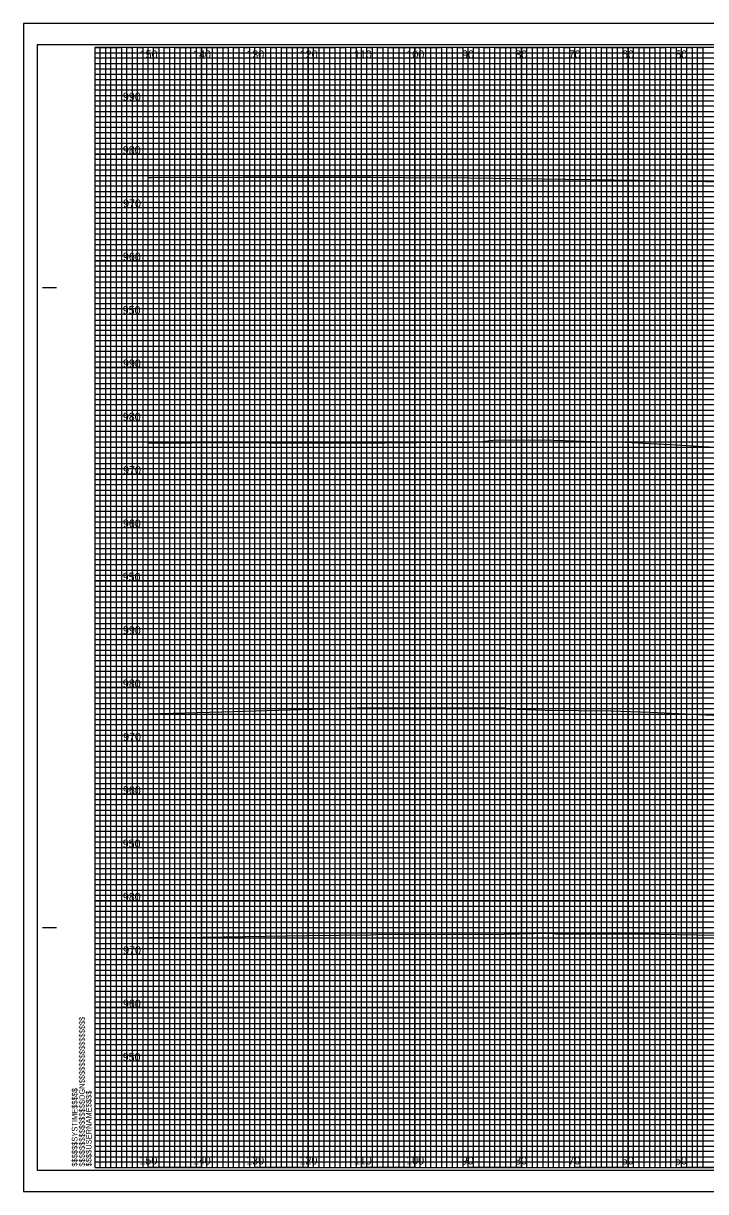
# Model space of a CAD drawing. Extents: x -13 to 760, y -5 to 1491.
# Drawn here: x 423.3 to 551.2, y -4.5 to 214.5 of the extents above; entities that cross this region are included whole.
import ezdxf

# ---------------------------------------------------------------- set-up
doc = ezdxf.new("R2010")
doc.units = 0
for name, color, linetype in [('Default', 7, 'Continuous'), ('Exist XS Ground Line', 7, 'Continuous'), ('Prop XS Elevation Labels', 7, 'Continuous'), ('Prop XS Offset Labels', 7, 'Continuous'), ('Sheet Cross Section CELL', 7, 'Continuous'), ('Sheet Cross Section Grid Major CELL', 7, 'Continuous'), ('Sheet Cross Section Grid Middle CELL', 7, 'Continuous'), ('Sheet Cross Section Grid Minor 1 CELL', 7, 'Continuous'), ('Sheet Cross Section Grid Minor 2 CELL', 7, 'Continuous'), ('Sheet Cutting Line CELL', 7, 'Continuous'), ('Sheet DOT Grid CELL', 7, 'Continuous'), ('Sheet Plot Border Inside CELL', 7, 'Continuous'), ('Sheet Plot Border Outside CELL', 7, 'Continuous')]:
    doc.layers.add(name, color=color, linetype=linetype)

msp = doc.modelspace()

# ---------------------------------------------------------------- linework, layer by layer
at = {"layer": 'Exist XS Ground Line'}
for points in [[(446.7, 185.58), (447.38, 185.58), (464.51, 185.68), (488.52, 185.69), (494.51, 185.63), (506.89, 185.52), (534.05, 185.16), (538.42, 185.1), (551.17, 184.85), (565.44, 184.4)], [(446.7, 185.58), (447.38, 185.58), (464.51, 185.68), (488.52, 185.69), (494.51, 185.63), (506.89, 185.52), (534.05, 185.16), (538.42, 185.1), (551.17, 184.85), (565.44, 184.4)], [(446.7, 135.8), (463.08, 135.92), (475.72, 135.81), (491.08, 135.84), (503.11, 135.97), (503.4, 135.97), (505.33, 135.93), (508.89, 136.08), (511.8, 136.43), (522.62, 136.37), (530.44, 136.14), (534.96, 136.04), (544.53, 135.53), (554.08, 135.02)], [(446.7, 135.8), (463.08, 135.92), (475.72, 135.81), (491.08, 135.84), (503.11, 135.97), (503.4, 135.97), (505.33, 135.93), (508.89, 136.08), (511.8, 136.43), (522.62, 136.37), (530.44, 136.14), (534.96, 136.04), (544.53, 135.53), (554.08, 135.02)], [(446.7, 85.04), (460.53, 85.47), (485.95, 86.21), (488.33, 86.22), (493.22, 86.2), (502.05, 86.22), (505.46, 86.21), (505.87, 86.19), (513.51, 86.18), (513.89, 86.05), (513.89, 86.03), (521.09, 85.78), (533.47, 85.6), (540.78, 85.35), (557.87, 84.58)], [(446.7, 85.04), (460.53, 85.47), (485.95, 86.21), (488.33, 86.22), (493.22, 86.2), (502.05, 86.22), (505.46, 86.21), (505.87, 86.19), (513.51, 86.18), (513.89, 86.05), (513.89, 86.03), (521.09, 85.78), (533.47, 85.6), (540.78, 85.35), (557.87, 84.58)], [(446.7, 43.2), (451.52, 43.13), (453.12, 43.15), (476.38, 43.49), (488.44, 43.67), (489.37, 43.69), (513.46, 43.78), (521.89, 43.93), (523.65, 43.76), (532.71, 43.85), (542.69, 43.76), (552.84, 43.56)], [(446.7, 43.2), (451.52, 43.13), (453.12, 43.15), (476.38, 43.49), (488.44, 43.67), (489.37, 43.69), (513.46, 43.78), (521.89, 43.93), (523.65, 43.76), (532.71, 43.85), (542.69, 43.76), (552.84, 43.56)]]:
    msp.add_lwpolyline(points, dxfattribs=at)
at = {"layer": 'Sheet Cross Section CELL'}
for p, q in [((426.9, 165), (429.4, 165)), ((427, 165), (429.5, 165)), ((426.9, 45), (429.4, 45)), ((427, 45), (429.5, 45)), ((436.7, 0), (436.7, 0)), ((436.7, 0), (436.7, 0)), ((436.7, 0), (436.7, 0)), ((436.7, 0), (436.7, 0)), ((436.7, 0), (436.7, 0)), ((436.7, 0), (436.7, 0)), ((436.7, 0), (436.7, 0))]:
    msp.add_line(p, q, dxfattribs=at)
msp.add_lwpolyline([(756.7, 210), (436.7, 210), (436.7, 0), (756.7, 0)], close=True, dxfattribs=at)
at = {"layer": 'Sheet Cross Section Grid Major CELL'}
for p, q in [((446.7, 210), (436.7, 210)), ((446.7, 0), (446.7, 210)), ((466.7, 210), (456.7, 210)), ((456.7, 210), (456.7, 0)), ((466.7, 0), (466.7, 210)), ((486.7, 210), (476.7, 210)), ((476.7, 210), (476.7, 0)), ((486.7, 0), (486.7, 210)), ((506.7, 210), (496.7, 210)), ((496.7, 210), (496.7, 0)), ((506.7, 0), (506.7, 210)), ((526.7, 210), (516.7, 210)), ((516.7, 210), (516.7, 0)), ((526.7, 0), (526.7, 210)), ((546.7, 210), (536.7, 210)), ((536.7, 210), (536.7, 0)), ((546.7, 0), (546.7, 210)), ((456.7, 0), (446.7, 0)), ((476.7, 0), (466.7, 0)), ((496.7, 0), (486.7, 0)), ((516.7, 0), (506.7, 0)), ((536.7, 0), (526.7, 0)), ((556.7, 0), (546.7, 0))]:
    msp.add_line(p, q, dxfattribs=at)
for points in [[(436.7, 200), (756.7, 200), (756.7, 190), (436.7, 190)], [(436.7, 180), (756.7, 180), (756.7, 170), (436.7, 170)], [(436.7, 160), (756.7, 160), (756.7, 150), (436.7, 150)], [(436.7, 140), (756.7, 140), (756.7, 130), (436.7, 130)], [(436.7, 120), (756.7, 120), (756.7, 110), (436.7, 110)], [(436.7, 100), (756.7, 100), (756.7, 90), (436.7, 90)], [(436.7, 80), (756.7, 80), (756.7, 70), (436.7, 70)], [(436.7, 60), (756.7, 60), (756.7, 50), (436.7, 50)], [(436.7, 40), (756.7, 40), (756.7, 30), (436.7, 30)], [(436.7, 20), (756.7, 20), (756.7, 10), (436.7, 10)]]:
    msp.add_lwpolyline(points, dxfattribs=at)
at = {"layer": 'Sheet Cross Section Grid Middle CELL'}
for points in [[(436.7, 210), (441.7, 210), (441.7, 0), (451.7, 0), (451.7, 210), (461.7, 210), (461.7, 0), (471.7, 0), (471.7, 210), (481.7, 210), (481.7, 0), (491.7, 0), (491.7, 210), (501.7, 210), (501.7, 0), (511.7, 0), (511.7, 210), (521.7, 210), (521.7, 0), (531.7, 0), (531.7, 210), (541.7, 210), (541.7, 0), (551.7, 0)], [(436.7, 205), (711.7, 205)], [(436.7, 185), (756.7, 185), (756.7, 195), (436.7, 195)], [(436.7, 165), (756.7, 165), (756.7, 175), (436.7, 175)], [(436.7, 145), (756.7, 145), (756.7, 155), (436.7, 155)], [(436.7, 125), (756.7, 125), (756.7, 135), (436.7, 135)], [(436.7, 105), (756.7, 105), (756.7, 115), (436.7, 115)], [(436.7, 85), (756.7, 85), (756.7, 95), (436.7, 95)], [(436.7, 65), (756.7, 65), (756.7, 75), (436.7, 75)], [(436.7, 45), (756.7, 45), (756.7, 55), (436.7, 55)], [(436.7, 25), (756.7, 25), (756.7, 35), (436.7, 35)], [(436.7, 5), (756.7, 5), (756.7, 15), (436.7, 15)]]:
    msp.add_lwpolyline(points, dxfattribs=at)
at = {"layer": 'Sheet Cross Section Grid Minor 1 CELL'}
for p, q in [((436.7, 209), (696.7, 209)), ((696.7, 207.98), (436.7, 207.98)), ((436.7, 207.98), (436.7, 207)), ((436.7, 207), (696.7, 207)), ((696.7, 205.89), (436.7, 205.89)), ((436.7, 205.89), (436.7, 204)), ((436.7, 204), (756.7, 204))]:
    msp.add_line(p, q, dxfattribs=at)
for points in [[(436.7, 203), (706.7, 203), (756.7, 203), (756.7, 202), (436.7, 202)], [(436.7, 201), (756.7, 201), (756.7, 199), (436.7, 199)], [(436.7, 198), (756.7, 198), (756.7, 197), (436.7, 196.98)], [(436.7, 196), (756.7, 196), (756.7, 194), (436.7, 194)], [(436.7, 193), (756.7, 193), (756.7, 192), (436.7, 192)], [(436.7, 191), (756.7, 191), (756.7, 189), (436.7, 189)], [(436.7, 188), (756.7, 188), (756.7, 187), (436.7, 187)], [(436.7, 186), (756.7, 186), (756.7, 184), (436.7, 184)], [(436.7, 183), (756.7, 183), (756.7, 182), (436.7, 182)], [(436.7, 181), (756.7, 181), (756.7, 179), (436.7, 179)], [(436.7, 178), (756.7, 178), (756.7, 177), (436.7, 177)], [(436.7, 176), (756.7, 176), (756.7, 173.95), (756.7, 173), (756.7, 172), (436.7, 172)], [(436.7, 174), (756.7, 174), (756.7, 173), (436.7, 173)], [(436.7, 171), (756.7, 171), (756.7, 169), (436.7, 169.03)], [(436.7, 169.03), (756.7, 169), (756.7, 168), (436.7, 168)], [(436.7, 167), (756.7, 167), (756.7, 166), (436.7, 166)], [(436.7, 164), (756.7, 164), (756.7, 163), (436.7, 163)], [(436.7, 162), (756.7, 162), (756.7, 161), (436.7, 161)], [(436.63, 158.89), (756.7, 158.89), (756.7, 157.88), (436.63, 157.88)], [(436.7, 157), (756.7, 157), (756.7, 156), (436.7, 156)], [(436.7, 154), (756.7, 154), (756.7, 153), (436.7, 153)], [(436.7, 152), (756.7, 152), (756.7, 151), (436.7, 151)], [(436.7, 149), (756.7, 149), (756.7, 148), (436.7, 148)], [(436.7, 147), (756.7, 147), (756.7, 146), (436.7, 146)], [(436.7, 144), (756.7, 144), (756.7, 143), (436.7, 143)], [(436.7, 142), (756.7, 142), (756.7, 141), (436.7, 141)], [(436.7, 139), (756.7, 139), (756.69, 137.98), (436.7, 138)], [(436.7, 137), (756.7, 137), (756.7, 136), (436.7, 136)], [(436.7, 134), (756.7, 134), (756.7, 133), (436.7, 133)], [(436.7, 132), (756.7, 132), (756.7, 131), (436.7, 131)], [(436.7, 129), (756.7, 129), (756.7, 128), (436.7, 128)], [(436.7, 127), (756.7, 127), (756.7, 126), (436.7, 126)], [(436.7, 124), (756.7, 124), (756.7, 123), (436.7, 123)], [(436.7, 122), (756.7, 122), (756.7, 121), (436.7, 121)], [(436.7, 119), (756.7, 119), (756.7, 118), (436.7, 118)], [(436.7, 116.99), (756.77, 116.91), (756.7, 116), (436.7, 116)], [(436.7, 114), (756.7, 114), (756.7, 113), (436.7, 113)], [(436.7, 112), (756.7, 112), (756.7, 111), (436.7, 111)], [(436.7, 109), (756.7, 109), (756.7, 108), (436.7, 108)], [(436.7, 107), (756.7, 107), (756.7, 106), (436.7, 106)], [(436.7, 104), (756.7, 104), (756.7, 103), (436.7, 103)], [(436.7, 102), (756.7, 102), (756.7, 101), (436.7, 101)], [(436.7, 99), (756.7, 99), (756.7, 98), (436.7, 98)], [(436.7, 97), (756.7, 97), (756.7, 96), (436.7, 96)], [(436.7, 94), (756.7, 94), (756.7, 93), (436.7, 93)], [(436.7, 92), (756.7, 92), (756.7, 91), (436.7, 91)], [(436.7, 89), (756.7, 89), (756.7, 88), (436.7, 88)], [(436.7, 87), (756.7, 87), (756.7, 86), (436.7, 86)], [(436.7, 84), (756.7, 84), (756.7, 83), (436.7, 83)], [(436.7, 82), (756.7, 82), (756.7, 81), (436.7, 81)], [(436.7, 79), (756.7, 79), (756.69, 77.98), (436.7, 78)], [(436.7, 77), (756.7, 77), (756.7, 76), (436.7, 76)], [(436.7, 74), (756.7, 74), (756.7, 73), (436.7, 73)], [(436.7, 72), (756.7, 72), (756.7, 71), (436.7, 71)], [(436.7, 69), (756.7, 69), (756.7, 68), (436.7, 68)], [(436.7, 67), (756.7, 67), (756.7, 66), (436.7, 66)], [(436.7, 64), (756.7, 64), (756.7, 63), (436.7, 63)], [(436.7, 62), (756.7, 62), (756.7, 61), (436.7, 61)], [(436.7, 59), (756.7, 59), (756.7, 58), (436.7, 58)], [(436.7, 56.99), (756.77, 56.91), (756.7, 56), (436.7, 56)], [(436.7, 54), (756.7, 54), (756.7, 53), (436.7, 53)], [(436.7, 52), (756.7, 52), (756.7, 51), (436.7, 51)], [(436.7, 49), (756.7, 49), (756.7, 48), (436.7, 48)], [(436.7, 47), (756.7, 47), (756.7, 46), (436.7, 46)], [(436.7, 44), (756.7, 44), (756.7, 43), (436.7, 43)], [(436.7, 42), (756.7, 42), (756.7, 41), (436.7, 41)], [(436.7, 39), (756.7, 39), (756.7, 38), (436.7, 38)], [(436.7, 37), (756.7, 37), (756.7, 36), (436.7, 36)], [(436.7, 34), (756.7, 34), (756.7, 33), (436.7, 33)], [(436.7, 32), (756.7, 32), (756.7, 31), (436.7, 31)], [(436.7, 29), (756.7, 29), (756.7, 28), (436.7, 28)], [(436.7, 27), (756.7, 27), (756.7, 26), (436.7, 26)], [(436.7, 24), (756.7, 24), (756.7, 23), (436.7, 23)], [(436.7, 22), (756.7, 22), (756.7, 21), (436.7, 21)], [(436.7, 19), (756.7, 19), (756.7, 18), (436.7, 18)], [(436.7, 17), (756.7, 17), (756.7, 16), (436.7, 16)], [(436.7, 14), (756.7, 14), (756.7, 13), (436.7, 13)], [(436.7, 12), (756.7, 12), (756.7, 11), (436.7, 11)], [(436.7, 9), (756.7, 9), (756.7, 8), (436.7, 8)], [(436.7, 7), (756.7, 7), (756.7, 6), (436.7, 6)], [(436.7, 4), (756.7, 4), (756.7, 3), (436.7, 3)], [(436.7, 2), (756.7, 2), (756.7, 1), (436.7, 1)]]:
    msp.add_lwpolyline(points, dxfattribs=at)
at = {"layer": 'Sheet Cross Section Grid Minor 2 CELL'}
for points in [[(436.7, 0), (437.7, 0), (437.7, 210), (438.7, 210), (438.7, 0)], [(438.7, 0), (439.7, 0), (439.7, 210), (440.7, 210), (440.7, 0)], [(441.7, 0), (442.7, 0), (442.7, 210), (443.7, 210), (443.7, 0)], [(443.7, 0), (444.7, 0), (444.7, 210), (445.7, 210), (445.7, 0)], [(446.7, 0), (447.7, 0), (447.7, 210), (448.7, 210), (448.7, 0)], [(448.7, 0), (449.7, 0), (449.7, 210), (450.7, 210), (450.7, 0)], [(451.7, 0), (452.7, 0), (452.7, 210), (453.7, 210), (453.7, 0)], [(453.7, 0), (454.7, 0), (454.7, 210), (455.7, 210), (455.7, 0)], [(456.7, 0), (457.7, 0), (457.7, 210), (458.7, 210), (458.7, 0)], [(458.7, 0), (459.7, 0), (459.7, 210), (460.7, 210), (460.7, 0)], [(461.7, 0), (462.7, 0), (462.7, 210), (463.7, 210), (463.7, 0)], [(463.7, 0), (464.7, 0), (464.7, 210), (465.7, 210), (465.7, 0)], [(466.7, 0), (467.7, 0), (467.7, 210), (468.7, 210), (468.7, 0)], [(468.7, 0), (469.7, 0), (469.7, 210), (470.7, 210), (470.7, 0)], [(471.7, 0), (472.7, 0), (472.7, 210), (473.7, 210), (473.7, 0)], [(473.7, 0), (474.7, 0), (474.7, 210), (475.7, 210), (475.7, 0)], [(476.7, 0), (477.7, 0), (477.7, 210), (478.7, 210), (478.7, 0)], [(478.7, 0), (479.7, 0), (479.7, 210), (480.7, 210), (480.7, 0)], [(481.7, 0), (482.7, 0), (482.7, 210), (483.7, 210), (483.7, 0)], [(483.7, 0), (484.7, 0), (484.7, 210), (485.7, 210), (485.7, 0)], [(486.7, 0), (487.7, 0), (487.7, 210), (488.7, 210), (488.7, 0)], [(488.7, 0), (489.7, 0), (489.7, 210), (490.7, 210), (490.7, 0)], [(491.7, 0), (492.7, 0), (492.7, 210), (493.7, 210), (493.7, 0)], [(493.7, 0), (494.7, 0), (494.7, 210), (495.7, 210), (495.7, 0)], [(496.7, 0), (497.7, 0), (497.7, 210), (498.7, 210), (498.7, 0)], [(498.7, 0), (499.7, 0), (499.7, 210), (500.7, 210), (500.7, 0)], [(501.7, 0), (502.7, 0), (502.7, 210), (503.7, 210), (503.7, 0)], [(503.7, 0), (504.7, 0), (504.7, 210), (505.7, 210), (505.7, 0)], [(506.7, 0), (507.7, 0), (507.7, 210), (508.7, 210), (508.7, 0)], [(508.7, 0), (509.7, 0), (509.7, 210), (510.7, 210), (510.7, 0)], [(511.7, 0), (512.7, 0), (512.7, 210), (513.7, 210), (513.7, 0)], [(513.7, 0), (514.7, 0), (514.7, 210), (515.7, 210), (515.7, 0)], [(516.7, 0), (517.7, 0), (517.7, 210), (518.7, 210), (518.7, 0)], [(518.7, 0), (519.7, 0), (519.7, 210), (520.7, 210), (520.7, 0)], [(521.7, 0), (522.7, 0), (522.7, 210), (523.7, 210), (523.7, 0)], [(523.7, 0), (524.7, 0), (524.7, 210), (525.7, 210), (525.7, 0)], [(526.7, 0), (527.7, 0), (527.7, 210), (528.7, 210), (528.7, 0)], [(528.7, 0), (529.7, 0), (529.7, 210), (530.7, 210), (530.7, 0)], [(531.7, 0), (532.7, 0), (532.7, 210), (533.7, 210), (533.7, 0)], [(533.7, 0), (534.7, 0), (534.7, 210), (535.7, 210), (535.7, 0)], [(536.7, 0), (537.7, 0), (537.7, 210), (538.7, 210), (538.7, 0)], [(538.7, 0), (539.7, 0), (539.7, 210), (540.7, 210), (540.7, 0)], [(541.7, 0), (542.7, 0), (542.7, 210), (543.7, 210), (543.7, 0)], [(543.7, 0), (544.7, 0), (544.7, 210), (545.7, 210), (545.7, 0)], [(546.7, 0), (547.7, 0), (547.7, 210), (548.7, 210), (548.7, 0)], [(548.7, 0), (549.7, 0), (549.7, 210), (550.7, 210), (550.7, 0)]]:
    msp.add_lwpolyline(points, dxfattribs=at)
at = {"layer": 'Sheet Cutting Line CELL'}
for p, q in [((760, 214.5), (423.3, 214.5)), ((423.3, 214.5), (423.3, -4.5)), ((423.3, -4.5), (760, -4.5))]:
    msp.add_line(p, q, dxfattribs=at)
at = {"layer": 'Sheet DOT Grid CELL'}
for p, q in [((446.7, 0), (446.7, 210)), ((456.7, 0), (456.7, 210)), ((466.7, 0), (466.7, 210)), ((476.7, 0), (476.7, 210)), ((486.7, 0), (486.7, 210)), ((496.7, 0), (496.7, 210)), ((506.7, 0), (506.7, 210)), ((516.7, 0), (516.7, 210)), ((526.7, 0), (526.7, 210)), ((536.7, 0), (536.7, 210)), ((546.7, 0), (546.7, 210)), ((436.7, 200), (756.7, 200)), ((436.7, 190), (756.7, 190)), ((436.7, 180), (756.7, 180)), ((436.7, 170), (756.7, 170)), ((436.7, 160), (756.7, 160)), ((436.7, 150), (756.7, 150)), ((436.7, 140), (756.7, 140)), ((436.7, 130), (756.7, 130)), ((436.7, 120), (756.7, 120)), ((436.7, 110), (756.7, 110)), ((436.7, 100), (756.7, 100)), ((436.7, 90), (756.7, 90)), ((436.7, 80), (756.7, 80)), ((436.7, 70), (756.7, 70)), ((436.7, 60), (756.7, 60)), ((436.7, 50), (756.7, 50)), ((436.7, 40), (756.7, 40)), ((436.7, 30), (756.7, 30)), ((436.7, 20), (756.7, 20)), ((436.7, 10), (756.7, 10))]:
    msp.add_line(p, q, dxfattribs=at)
at = {"layer": 'Sheet Plot Border Inside CELL'}
msp.add_lwpolyline([(425.9, -0.5), (759.1, -0.5), (759.1, 210.5), (425.9, 210.5)], close=True, dxfattribs=at)
at = {"layer": 'Sheet Plot Border Outside CELL'}
msp.add_lwpolyline([(423.3, -4.5), (760, -4.5), (760, 214.5), (423.3, 214.5)], close=True, dxfattribs=at)

# ---------------------------------------------------------------- texts
at = {"layer": 'Default'}
for p in [(446.7, 160), (446.7, 110), (446.7, 60), (446.7, 20)]:
    msp.add_text('-', height=0.0001, dxfattribs=at).set_placement(p)
at = {"layer": 'Prop XS Elevation Labels'}
for s, p in [('990', (441.96, 200)), ('980', (441.94, 190)), ('970', (442, 180)), ('960', (441.96, 170)), ('950', (441.92, 160)), ('990', (441.96, 150)), ('980', (441.94, 140)), ('970', (442, 130)), ('960', (441.96, 120)), ('950', (441.92, 110)), ('990', (441.96, 100)), ('980', (441.94, 90)), ('970', (442, 80)), ('960', (441.96, 70)), ('950', (441.92, 60)), ('980', (441.94, 50)), ('970', (442, 40)), ('960', (441.96, 30)), ('950', (441.92, 20))]:
    msp.add_text(s, height=1.5, dxfattribs=at).set_placement(p)
at = {"layer": 'Prop XS Offset Labels'}
for s, p in [('150', (445.11, 207.93)), ('140', (455.11, 207.93)), ('130', (465.11, 207.93)), ('120', (475.11, 207.93)), ('110', (485.29, 207.93)), ('100', (495.11, 207.93)), ('90', (505.53, 207.93)), ('80', (515.53, 207.93)), ('70', (525.53, 207.93)), ('60', (535.53, 207.93)), ('50', (545.53, 207.93)), ('150', (445.07, 0.59)), ('140', (455.07, 0.59)), ('130', (465.07, 0.59)), ('120', (475.07, 0.59)), ('110', (485.25, 0.59)), ('100', (495.07, 0.59)), ('90', (505.48, 0.59)), ('80', (515.48, 0.59)), ('70', (525.48, 0.59)), ('60', (535.48, 0.59)), ('50', (545.48, 0.59))]:
    msp.add_text(s, height=1.5, dxfattribs=at).set_placement(p)
at = {"layer": 'Sheet Cross Section CELL'}
for s, p in [('$$$$$$$$$$$$$$$$DGN$$$$$$$$$$$$$$$$', (434.82, 0.18)), ('$$$$$$SYSTIME$$$$$', (433.44, 0.18)), ('$$$$USERNAME$$$$', (436.08, 0.23))]:
    msp.add_text(s, height=1.05, rotation=90, dxfattribs=at).set_placement(p)

doc.saveas('drawing.dxf')
